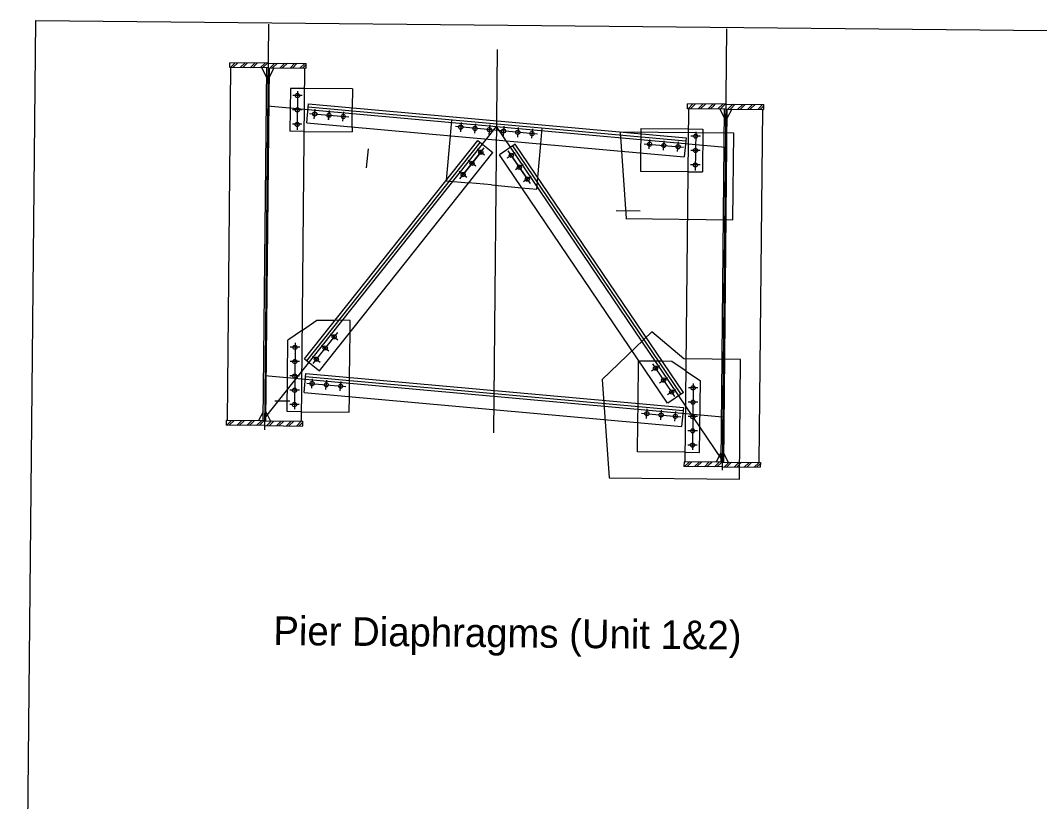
# Model space of a CAD drawing. Extents: x 632066 to 633140, y 373235 to 381884.
# Drawn here: x 632199.99 to 632217.79, y 378389.8 to 378403.44 of the extents above; entities that cross this region are included whole.
import ezdxf

# ---------------------------------------------------------------- set-up
doc = ezdxf.new("R2010")
doc.units = 0
for name, color, linetype in [('BD-EXIST-COSS', 7, 'Continuous'), ('BD-EXIST-OSB', 7, 'Continuous'), ('BD-LEGEND', 7, 'Continuous'), ('BD-PROP-COSS', 7, 'Continuous'), ('BD-PROP-OSB', 7, 'Continuous')]:
    doc.layers.add(name, color=color, linetype=linetype)

msp = doc.modelspace()

# ---------------------------------------------------------------- linework, layer by layer
at = {"layer": 'BD-EXIST-OSB'}
for p, q in [((632203.649, 378402.62), (632203.65, 378402.703)), ((632204.316, 378402.697), (632203.65, 378402.703)), ((632204.316, 378402.697), (632204.983, 378402.69)), ((632204.982, 378402.607), (632204.983, 378402.69)), ((632203.608, 378396.453), (632203.67, 378402.62)), ((632204.315, 378402.613), (632203.649, 378402.62)), ((632204.211, 378402.614), (632204.293, 378402.447)), ((632204.233, 378396.447), (632204.295, 378402.614)), ((632204.336, 378402.613), (632204.275, 378396.447)), ((632204.315, 378402.613), (632204.982, 378402.607)), ((632204.42, 378402.612), (632204.335, 378402.446)), ((632204.9, 378396.441), (632204.961, 378402.607)), ((632204.708, 378402.255), (632204.7, 378401.505)), ((632204.958, 378402.253), (632204.708, 378402.255)), ((632205.791, 378402.244), (632204.958, 378402.253)), ((632205.791, 378402.244), (632205.788, 378401.917)), ((632204.993, 378401.654), (632205.023, 378401.986)), ((632205.019, 378401.934), (632211.611, 378401.338)), ((632205.023, 378401.986), (632211.616, 378401.39)), ((632205.784, 378401.582), (632205.788, 378401.917)), ((632211.642, 378401.9), (632211.643, 378401.984)), ((632212.31, 378401.977), (632211.643, 378401.984)), ((632212.31, 378401.977), (632212.976, 378401.971)), ((632212.975, 378401.887), (632212.976, 378401.971)), ((632211.602, 378395.734), (632211.663, 378401.9)), ((632212.309, 378401.894), (632211.642, 378401.9)), ((632212.205, 378401.895), (632212.286, 378401.727)), ((632212.227, 378395.728), (632212.288, 378401.894)), ((632212.33, 378401.894), (632212.268, 378395.727)), ((632212.309, 378401.894), (632212.975, 378401.887)), ((632212.413, 378401.893), (632212.328, 378401.727)), ((632212.893, 378395.721), (632212.954, 378401.887)), ((632204.993, 378401.654), (632211.586, 378401.058)), ((632205.784, 378401.582), (632205.784, 378401.495)), ((632207.501, 378401.427), (632207.527, 378401.707)), ((632209.078, 378401.284), (632209.104, 378401.565)), ((632204.95, 378401.503), (632204.7, 378401.505)), ((632204.95, 378401.503), (632205.784, 378401.495)), ((632207.431, 378400.65), (632207.501, 378401.427)), ((632210.825, 378401.461), (632210.822, 378401.127)), ((632210.826, 378401.554), (632210.825, 378401.461)), ((632210.826, 378401.554), (632211.659, 378401.546)), ((632211.616, 378401.39), (632211.586, 378401.058)), ((632211.659, 378401.546), (632211.909, 378401.544)), ((632211.909, 378401.544), (632211.902, 378400.794)), ((632204.952, 378397.53), (632207.981, 378401.342)), ((632204.993, 378397.498), (632208.022, 378401.309)), ((632207.981, 378401.342), (632208.242, 378401.134)), ((632208.632, 378401.281), (632208.356, 378401.094)), ((632211.527, 378396.917), (632208.589, 378401.252)), ((632211.57, 378396.946), (632208.632, 378401.281)), ((632209.026, 378400.7), (632209.078, 378401.284)), ((632205.213, 378397.323), (632208.242, 378401.134)), ((632211.294, 378396.759), (632208.356, 378401.094)), ((632210.822, 378401.127), (632210.819, 378400.804)), ((632209.008, 378400.497), (632209.026, 378400.7)), ((632211.652, 378400.796), (632210.819, 378400.804)), ((632211.652, 378400.796), (632211.902, 378400.794)), ((632207.431, 378400.65), (632207.43, 378400.639)), ((632207.43, 378400.639), (632207.82, 378400.603)), ((632208.219, 378400.568), (632207.82, 378400.603)), ((632208.219, 378400.568), (632208.745, 378400.52)), ((632208.745, 378400.52), (632209.008, 378400.497)), ((632204.916, 378398.034), (632205.168, 378398.209)), ((632205.168, 378398.209), (632205.489, 378398.206)), ((632205.751, 378398.203), (632205.489, 378398.206)), ((632205.749, 378397.997), (632205.751, 378398.203)), ((632204.916, 378398.034), (632204.664, 378397.86)), ((632204.652, 378396.61), (632204.664, 378397.86)), ((632205.741, 378397.208), (632205.749, 378397.997)), ((632204.952, 378397.53), (632205.213, 378397.323)), ((632210.778, 378396.754), (632210.786, 378397.492)), ((632210.797, 378397.492), (632210.786, 378397.492)), ((632211.203, 378397.488), (632210.797, 378397.492)), ((632211.369, 378397.486), (632211.203, 378397.488)), ((632211.617, 378397.317), (632211.369, 378397.486)), ((632211.617, 378397.317), (632211.866, 378397.148)), ((632204.947, 378396.944), (632204.977, 378397.276)), ((632204.972, 378397.225), (632211.565, 378396.631)), ((632204.977, 378397.276), (632211.569, 378396.683)), ((632205.738, 378396.873), (632205.741, 378397.208)), ((632211.853, 378395.898), (632211.866, 378397.148)), ((632204.947, 378396.944), (632211.539, 378396.351)), ((632211.572, 378396.943), (632211.296, 378396.756)), ((632205.735, 378396.599), (632205.738, 378396.873)), ((632204.15, 378396.448), (632204.235, 378396.614)), ((632204.358, 378396.446), (632204.277, 378396.613)), ((632204.902, 378396.607), (632204.652, 378396.61)), ((632204.902, 378396.607), (632205.735, 378396.599)), ((632210.775, 378396.42), (632210.778, 378396.754)), ((632211.569, 378396.683), (632211.539, 378396.351)), ((632203.588, 378396.454), (632203.587, 378396.37)), ((632204.254, 378396.447), (632203.588, 378396.454)), ((632204.254, 378396.447), (632204.921, 378396.44)), ((632204.921, 378396.44), (632204.92, 378396.357)), ((632210.77, 378395.909), (632210.775, 378396.42)), ((632204.253, 378396.364), (632203.587, 378396.37)), ((632204.253, 378396.364), (632204.92, 378396.357)), ((632211.603, 378395.901), (632210.77, 378395.909)), ((632211.603, 378395.901), (632211.853, 378395.898)), ((632212.143, 378395.729), (632212.228, 378395.894)), ((632212.352, 378395.726), (632212.27, 378395.894)), ((632211.581, 378395.734), (632211.58, 378395.651)), ((632212.247, 378395.727), (632211.581, 378395.734)), ((632212.247, 378395.727), (632212.914, 378395.721)), ((632212.914, 378395.721), (632212.913, 378395.638)), ((632212.247, 378395.644), (632211.58, 378395.651)), ((632212.247, 378395.644), (632212.913, 378395.638))]:
    msp.add_line(p, q, dxfattribs=at)
for centre in [(632204.831, 378402.129), (632204.829, 378401.879), (632205.133, 378401.808), (632205.382, 378401.786), (632205.631, 378401.763), (632204.826, 378401.625), (632207.682, 378401.578), (632207.931, 378401.555), (632208.18, 378401.533), (632208.429, 378401.51), (632208.678, 378401.488), (632208.927, 378401.465), (632211.783, 378401.42), (632210.979, 378401.28), (632211.228, 378401.257), (632211.477, 378401.235), (632211.781, 378401.17), (632208.034, 378401.14), (632208.564, 378401.084), (632207.878, 378400.945), (632208.705, 378400.877), (632211.778, 378400.916), (632207.723, 378400.749), (632208.845, 378400.67), (632205.472, 378397.916), (632204.788, 378397.733), (632205.316, 378397.72), (632204.785, 378397.483), (632205.161, 378397.525), (632211.083, 378397.367), (632204.783, 378397.23), (632205.086, 378397.099), (632205.335, 378397.077), (632211.224, 378397.16), (632204.78, 378396.983), (632205.584, 378397.054), (632211.364, 378396.953), (632211.739, 378397.024), (632204.778, 378396.733), (632211.737, 378396.774), (632210.932, 378396.573), (632211.181, 378396.551), (632211.43, 378396.528), (632211.734, 378396.521), (632211.732, 378396.274), (632211.729, 378396.024)]:
    msp.add_circle(centre, 0.0365, dxfattribs=at)
at = {"layer": 'BD-LEGEND'}
for p, q in [((632203.659, 378402.62), (632203.743, 378402.702)), ((632203.703, 378402.619), (632203.787, 378402.702)), ((632203.833, 378402.618), (632203.917, 378402.701)), ((632203.876, 378402.618), (632203.96, 378402.7)), ((632204.006, 378402.616), (632204.091, 378402.699)), ((632204.05, 378402.616), (632204.106, 378402.671)), ((632204.106, 378402.671), (632204.134, 378402.698)), ((632204.18, 378402.615), (632204.264, 378402.697)), ((632204.223, 378402.614), (632204.308, 378402.697)), ((632204.354, 378402.613), (632204.438, 378402.695)), ((632204.397, 378402.613), (632204.481, 378402.695)), ((632204.527, 378402.611), (632204.611, 378402.694)), ((632204.571, 378402.611), (632204.655, 378402.693)), ((632204.701, 378402.61), (632204.785, 378402.692)), ((632204.744, 378402.609), (632204.828, 378402.692)), ((632204.874, 378402.608), (632204.959, 378402.69)), ((632204.918, 378402.607), (632204.983, 378402.671)), ((632211.652, 378401.9), (632211.737, 378401.983)), ((632211.696, 378401.9), (632211.78, 378401.982)), ((632211.826, 378401.899), (632211.91, 378401.981)), ((632211.869, 378401.898), (632211.954, 378401.981)), ((632212, 378401.897), (632212.084, 378401.979)), ((632212.043, 378401.896), (632212.099, 378401.952)), ((632212.099, 378401.952), (632212.127, 378401.979)), ((632212.173, 378401.895), (632212.257, 378401.978)), ((632212.217, 378401.895), (632212.301, 378401.977)), ((632212.347, 378401.893), (632212.431, 378401.976)), ((632212.39, 378401.893), (632212.474, 378401.976)), ((632212.52, 378401.892), (632212.605, 378401.974)), ((632212.564, 378401.891), (632212.648, 378401.974)), ((632212.694, 378401.89), (632212.778, 378401.973)), ((632212.737, 378401.89), (632212.822, 378401.972)), ((632212.868, 378401.888), (632212.952, 378401.971)), ((632212.911, 378401.888), (632212.976, 378401.952)), ((632203.597, 378396.37), (632203.681, 378396.453)), ((632203.64, 378396.37), (632203.725, 378396.452)), ((632203.771, 378396.368), (632203.855, 378396.451)), ((632203.814, 378396.368), (632203.898, 378396.451)), ((632203.944, 378396.367), (632204.028, 378396.449)), ((632203.988, 378396.366), (632204.044, 378396.421)), ((632204.044, 378396.421), (632204.072, 378396.449)), ((632204.118, 378396.365), (632204.202, 378396.448)), ((632204.161, 378396.365), (632204.245, 378396.447)), ((632204.291, 378396.363), (632204.376, 378396.446)), ((632204.335, 378396.363), (632204.419, 378396.445)), ((632204.465, 378396.362), (632204.549, 378396.444)), ((632204.508, 378396.361), (632204.593, 378396.444)), ((632204.639, 378396.36), (632204.723, 378396.442)), ((632204.682, 378396.359), (632204.766, 378396.442)), ((632204.812, 378396.358), (632204.896, 378396.441)), ((632204.856, 378396.358), (632204.921, 378396.421)), ((632211.59, 378395.651), (632211.674, 378395.733)), ((632211.634, 378395.65), (632211.718, 378395.733)), ((632211.764, 378395.649), (632211.848, 378395.731)), ((632211.807, 378395.649), (632211.891, 378395.731)), ((632211.937, 378395.647), (632212.022, 378395.73)), ((632211.981, 378395.647), (632212.037, 378395.702)), ((632212.037, 378395.702), (632212.065, 378395.729)), ((632212.111, 378395.646), (632212.195, 378395.728)), ((632212.154, 378395.645), (632212.239, 378395.728)), ((632212.285, 378395.644), (632212.369, 378395.726)), ((632212.328, 378395.643), (632212.412, 378395.726)), ((632212.458, 378395.642), (632212.542, 378395.725)), ((632212.502, 378395.642), (632212.586, 378395.724)), ((632212.632, 378395.64), (632212.716, 378395.723)), ((632212.675, 378395.64), (632212.759, 378395.722)), ((632212.805, 378395.639), (632212.89, 378395.721)), ((632212.849, 378395.638), (632212.914, 378395.702))]:
    msp.add_line(p, q, dxfattribs=at)
at = {"layer": 'BD-PROP-COSS'}
for p, q in [((632210.464, 378401.492), (632210.571, 378399.98)), ((632212.45, 378401.473), (632210.464, 378401.492)), ((632212.435, 378399.961), (632212.45, 378401.473)), ((632206.063, 378401.196), (632206.033, 378400.864)), ((632210.812, 378400.11), (632210.398, 378400.114)), ((632210.567, 378399.98), (632212.435, 378399.961)), ((632211.016, 378398), (632210.15, 378397.173)), ((632211.578, 378397.531), (632211.016, 378398)), ((632212.565, 378397.519), (632211.578, 378397.531)), ((632212.549, 378395.429), (632212.565, 378397.519)), ((632210.15, 378397.173), (632210.271, 378395.452)), ((632204.695, 378396.789), (632204.436, 378396.792)), ((632210.271, 378395.452), (632212.549, 378395.429))]:
    msp.add_line(p, q, dxfattribs=at)
msp.add_lwpolyline([(632200.26, 378403.442), (632235.587, 378403.091), (632235.319, 378376.155), (632199.993, 378376.506)], close=True, dxfattribs=at)
at = {"layer": 'BD-PROP-OSB'}
for p, q in [((632204.323, 378403.375), (632204.253, 378396.292)), ((632212.323, 378403.295), (632212.246, 378395.584)), ((632208.319, 378402.935), (632208.252, 378396.24)), ((632204.915, 378402.128), (632204.748, 378402.13)), ((632204.832, 378402.205), (632204.826, 378401.531)), ((632204.309, 378401.947), (632212.302, 378401.227)), ((632204.912, 378401.878), (632204.746, 378401.88)), ((632205.039, 378401.817), (632205.725, 378401.755)), ((632205.125, 378401.725), (632205.14, 378401.891)), ((632205.374, 378401.703), (632205.389, 378401.869)), ((632205.376, 378401.703), (632205.388, 378401.869)), ((632205.623, 378401.68), (632205.638, 378401.846)), ((632204.255, 378396.489), (632208.305, 378401.587)), ((632204.91, 378401.628), (632204.743, 378401.63)), ((632209.022, 378401.457), (632207.588, 378401.586)), ((632207.69, 378401.661), (632207.675, 378401.495)), ((632207.939, 378401.638), (632207.924, 378401.472)), ((632208.188, 378401.616), (632208.173, 378401.45)), ((632212.248, 378395.769), (632208.305, 378401.587)), ((632208.437, 378401.593), (632208.422, 378401.427)), ((632208.686, 378401.571), (632208.671, 378401.405)), ((632208.935, 378401.548), (632208.92, 378401.382)), ((632211.866, 378401.419), (632211.7, 378401.421)), ((632211.784, 378401.496), (632211.777, 378400.822)), ((632207.664, 378400.675), (632208.092, 378401.214)), ((632210.884, 378401.288), (632211.571, 378401.227)), ((632210.971, 378401.197), (632210.986, 378401.363)), ((632211.22, 378401.174), (632211.235, 378401.34)), ((632211.469, 378401.152), (632211.484, 378401.318)), ((632208.034, 378401.14), (632207.723, 378400.749)), ((632208.099, 378401.088), (632207.968, 378401.192)), ((632208.633, 378401.131), (632208.495, 378401.038)), ((632208.898, 378400.592), (632208.511, 378401.163)), ((632208.564, 378401.084), (632208.845, 378400.67)), ((632211.864, 378401.169), (632211.697, 378401.171)), ((632207.943, 378400.893), (632207.813, 378400.996)), ((632208.774, 378400.924), (632208.636, 378400.831)), ((632211.861, 378400.919), (632211.695, 378400.921)), ((632207.788, 378400.697), (632207.657, 378400.801)), ((632208.914, 378400.717), (632208.776, 378400.624)), ((632205.531, 378397.99), (632205.102, 378397.45)), ((632205.407, 378397.968), (632205.537, 378397.864)), ((632204.871, 378397.733), (632204.704, 378397.734)), ((632204.789, 378397.809), (632204.777, 378396.65)), ((632205.251, 378397.772), (632205.381, 378397.669)), ((632204.869, 378397.483), (632204.702, 378397.484)), ((632205.095, 378397.576), (632205.226, 378397.473)), ((632211.014, 378397.32), (632211.152, 378397.414)), ((632211.03, 378397.445), (632211.417, 378396.875)), ((632204.259, 378397.239), (632212.255, 378396.519)), ((632204.866, 378397.233), (632204.699, 378397.234)), ((632205.079, 378397.016), (632205.094, 378397.182)), ((632205.328, 378396.994), (632205.343, 378397.16)), ((632205.577, 378396.971), (632205.592, 378397.137)), ((632211.155, 378397.113), (632211.293, 378397.207)), ((632204.864, 378396.983), (632204.697, 378396.984)), ((632204.992, 378397.108), (632205.678, 378397.046)), ((632211.295, 378396.906), (632211.433, 378397)), ((632211.823, 378397.023), (632211.656, 378397.025)), ((632211.74, 378397.1), (632211.729, 378395.941)), ((632211.82, 378396.773), (632211.654, 378396.775)), ((632204.861, 378396.733), (632204.695, 378396.734)), ((632210.838, 378396.581), (632211.524, 378396.52)), ((632210.924, 378396.49), (632210.939, 378396.656)), ((632211.173, 378396.468), (632211.188, 378396.634)), ((632211.422, 378396.445), (632211.437, 378396.611)), ((632211.818, 378396.523), (632211.651, 378396.525)), ((632211.815, 378396.273), (632211.649, 378396.275)), ((632211.813, 378396.023), (632211.646, 378396.025))]:
    msp.add_line(p, q, dxfattribs=at)

# ---------------------------------------------------------------- texts
at = {"layer": 'BD-EXIST-COSS'}
msp.add_text('Pier Diaphragms (Unit 1&2)', height=0.5, rotation=359.4304, dxfattribs=at).set_placement((632204.408, 378392.534))

doc.saveas('drawing.dxf')
